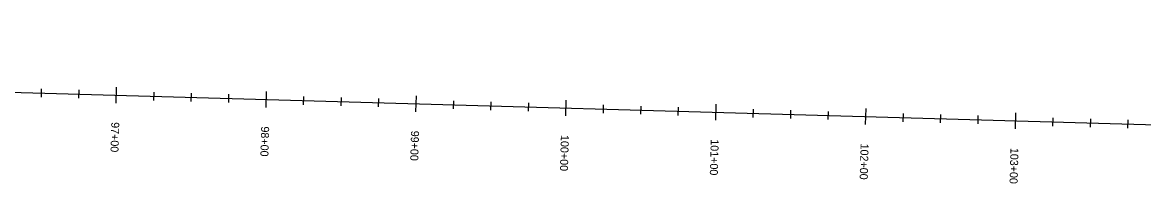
# Model space of a CAD drawing. Extents: x 2301963 to 2307911, y 760768 to 761974.
# Drawn here: x 2306429 to 2307177, y 760791 to 760898 of the extents above; entities that cross this region are included whole.
import ezdxf

# ---------------------------------------------------------------- set-up
doc = ezdxf.new("R2010")
doc.units = 0
for name, color, linetype in [('Default', 7, 'Continuous'), ('Draft_Station Labels Major', 7, 'Continuous'), ('Draft_Station Ticks Major', 7, 'Continuous'), ('Draft_Station Ticks Minor', 7, 'Continuous'), ('Geom_Secondary', 7, 'Continuous')]:
    doc.layers.add(name, color=color, linetype=linetype)

msp = doc.modelspace()

# ---------------------------------------------------------------- linework, layer by layer
at = {"layer": 'Default'}
msp.add_line((2304792.58, 760898.19), (2307901.31, 760809.5), dxfattribs=at)
at = {"layer": 'Draft_Station Ticks Major'}
for p, q in [((2306491.55, 760855.06), (2306491.25, 760844.45)), ((2306591.51, 760852.21), (2306591.21, 760841.59)), ((2306691.47, 760849.36), (2306691.17, 760838.74)), ((2306791.43, 760846.51), (2306791.13, 760835.89)), ((2306891.39, 760843.66), (2306891.09, 760833.04)), ((2306991.35, 760840.8), (2306991.05, 760830.19)), ((2307091.31, 760837.95), (2307091.01, 760827.34))]:
    msp.add_line(p, q, dxfattribs=at)
at = {"layer": 'Draft_Station Ticks Minor'}
for p, q in [((2306441.5, 760853.91), (2306441.34, 760848.39)), ((2306466.49, 760853.2), (2306466.33, 760847.68)), ((2306516.47, 760851.77), (2306516.31, 760846.25)), ((2306541.46, 760851.06), (2306541.3, 760845.54)), ((2306566.45, 760850.34), (2306566.29, 760844.83)), ((2306616.43, 760848.92), (2306616.27, 760843.4)), ((2306641.42, 760848.21), (2306641.26, 760842.69)), ((2306666.41, 760847.49), (2306666.25, 760841.97)), ((2306716.39, 760846.07), (2306716.23, 760840.55)), ((2306741.38, 760845.35), (2306741.22, 760839.84)), ((2306766.37, 760844.64), (2306766.21, 760839.12)), ((2306816.35, 760843.22), (2306816.19, 760837.7)), ((2306841.34, 760842.5), (2306841.18, 760836.98)), ((2306866.33, 760841.79), (2306866.17, 760836.27)), ((2306916.31, 760840.36), (2306916.15, 760834.85)), ((2306941.3, 760839.65), (2306941.14, 760834.13)), ((2306966.29, 760838.94), (2306966.13, 760833.42)), ((2307016.27, 760837.51), (2307016.11, 760831.99)), ((2307041.26, 760836.8), (2307041.1, 760831.28)), ((2307066.25, 760836.09), (2307066.09, 760830.57)), ((2307116.23, 760834.66), (2307116.07, 760829.14)), ((2307141.22, 760833.95), (2307141.06, 760828.43)), ((2307166.21, 760833.23), (2307166.05, 760827.72))]:
    msp.add_line(p, q, dxfattribs=at)
at = {"layer": 'Geom_Secondary'}
msp.add_line((2304792.58, 760898.19), (2307901.31, 760809.5), dxfattribs=at)

# ---------------------------------------------------------------- texts
at = {"layer": 'Draft_Station Labels Major'}
for s, p in [('97+00', (2306488.22, 760831.81)), ('98+00', (2306588.18, 760828.96)), ('99+00', (2306688.14, 760826.1)), ('100+00', (2306788.1, 760823.25)), ('101+00', (2306888.06, 760820.4)), ('102+00', (2306988.02, 760817.55)), ('103+00', (2307087.98, 760814.7))]:
    msp.add_text(s, height=5.34, rotation=268.36584, dxfattribs=at).set_placement(p)

doc.saveas('drawing.dxf')
